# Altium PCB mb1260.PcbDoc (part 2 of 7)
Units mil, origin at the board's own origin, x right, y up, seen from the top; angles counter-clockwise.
Board outline 3189.01 x 3818.89 mil, 6 copper layers (TOP, L2_GND, L3_VCC, L4_SIG, L5_GND, BOTTOM), stack 62.2 mil thick; 308 components, 287 nets, 1220 pads, 851 vias.
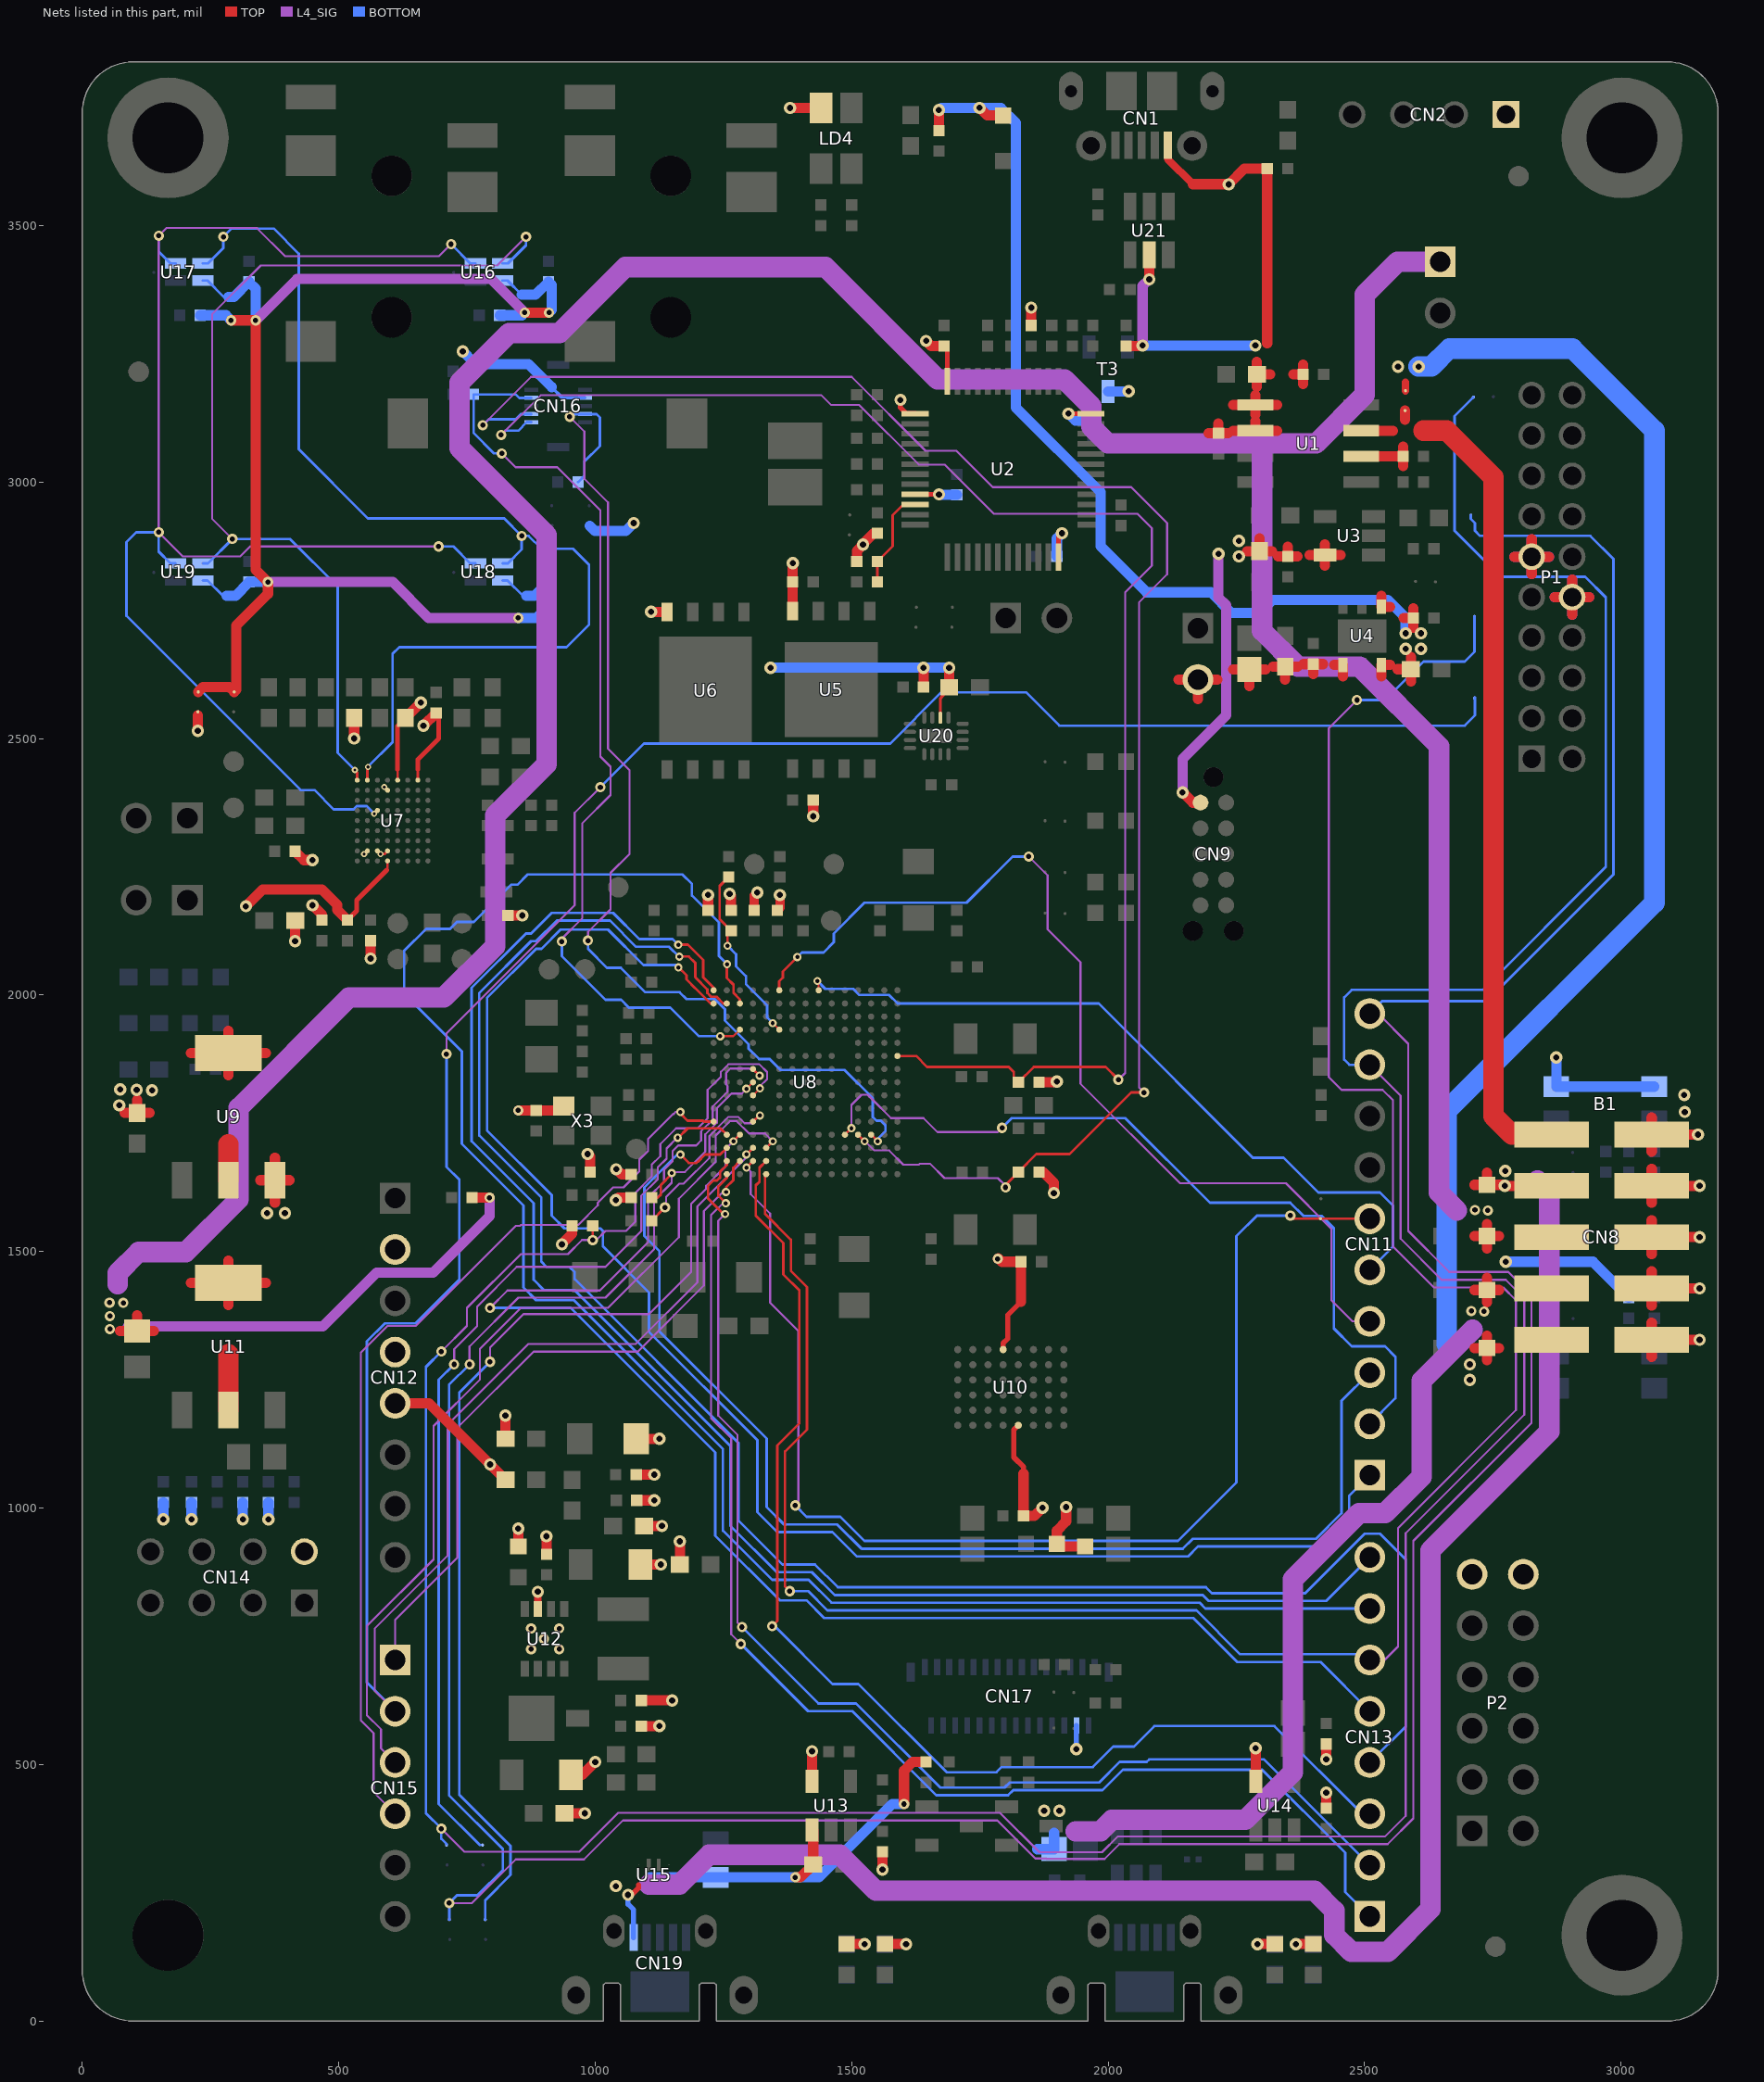
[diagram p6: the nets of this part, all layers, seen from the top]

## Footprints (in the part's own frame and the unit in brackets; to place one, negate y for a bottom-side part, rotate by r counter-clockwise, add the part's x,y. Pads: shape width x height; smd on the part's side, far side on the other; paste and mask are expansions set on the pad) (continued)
SQT-110-01-F-D-RA [mil] "SQT-110-01-F-D-RA"
  rect 52x52 hole 36: 1(-354.33,-39.37)
  round 52 hole 36: 2(-275.59,-39.37) 3(-196.85,-39.37) 4(-118.11,-39.37) 5(-39.37,-39.37) 6(39.37,-39.37) 7(118.11,-39.37) 8(196.85,-39.37) 9(275.59,-39.37) 10(354.33,-39.37) 11(-354.33,39.37) 12(-275.59,39.37) 13(-196.85,39.37) 14(-118.11,39.37) 15(-39.37,39.37) 16(39.37,39.37) 17(118.11,39.37) 18(196.85,39.37) 19(275.59,39.37) 20(354.33,39.37)
  silkscreen extent -400,-51 400,339, body extent -398,-69 407,341, height 150
SSW-106-02-F-D-RA [mil] "SSW-106-02-F-D-RA"
  rect 60x60 hole 40: 1(0,0)
  round 60 hole 40: 2(100,0) 3(200,0) 4(300,0) 5(400,0) 6(500,0) 7(0,100) 8(100,100) 9(200,100) 10(300,100) 11(400,100) 12(500,100)
  silkscreen extent -70,-13 560,495, body extent -60,-35 560,494, height 150
TACT_4SM_3R5X5R5 [mil] "TACT_4SM_3R5X5R5"
  rect 40x50 smd: 1(-33.46,95.47) 2(33.46,95.47) 3(-33.46,-95.47) 4(33.46,-95.47)
  silkscreen extent -69,-93 69,156, body extent -70,-125 70,125, height 150
TAN-A [mil] "TAN-A"
  rect 50x60 smd: 1(55,0) 2(-55,0)
  silkscreen extent -95,-45 110,45
TC2050-IDC-NL [mil] "TC2050-IDC-NL"
  round 31 smd paste-50: 1(-100,-25) 2(-50,-25) 3(0,-25) 4(50,-25) 5(100,-25) 6(100,25) 7(50,25) 8(0,25) 9(-50,25) 10(-100,25)
  round 39 hole 39: " "(-150,0) " "(150,-39.96) " "(150,39.96)
  TOP pour cut-out: -100,22.4 -100,-10.6 -89.5,-21.1 -15,-21.1 -6.9,-13 5.2,-13 13.3,-21.1 87.4,-21.1 100,-8.5 100,22.4 -100,22.4
  Keep-Out Layer circle w1: c-150,0 r35.43
  Keep-Out Layer circle w1: c150,39.96 r35.43
  Keep-Out Layer circle w1: c150,-39.96 r35.43
  silkscreen extent -245,-133 245,133, body extent -245,-133 245,133, height 150
TP_C40 [mil] "TP_C40"
  round 40 smd paste-50: 1(0,0)
  silkscreen extent -29,-29 29,29, body extent -31,-31 31,31, height 150
TSM-105-01-S-DV [mil] "TSM-105-01-S-DV"
  rect 50x145 smd: 1(-200,-97.44) 2(-200,97.44) 3(-100,-97.44) 4(-100,97.44) 5(0,-97.44) 6(0,97.44) 7(100,-97.44) 8(100,97.44) 9(200,-97.44) 10(200,97.44)
  silkscreen extent -250,-211 250,100, body extent -250,-175 250,175, height 150
XTAL_2SM_3R2X1R5 [mil] "XTAL_2SM_3R2X1R5"
  rect 51x63 smd: 1(-45.28,0) 2(45.28,0)
  silkscreen extent -85,-45 85,45, body extent -71,-30 72,32, height 150
XTAL_2SM_3R2X2R5_H1 [mil] "XTAL_2SM_3R2X2R5_H1"
  rect 71x106 smd: 1(-45.28,0) 2(45.28,0)
  silkscreen extent -95,-65 95,65, body extent -84,-56 84,56, height 150

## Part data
B1 B2: "EVQP2 - 4.7mm x 3.5 mm SMD Light Touch Switch"
C1 C2 C5 C7 C10 C12 C13 C14 C16 C23 C30 C32 C33 C36 C37 C38 C39 C40 C41 C42 C44 C45 C46 C47 C52 C53 C55 C56 C59 C60 C61 C62 C63 C69 C70 C71 C79 C80 C81 C82 C83 C84 C85 C86 C87 C93: library part Cap_100nF_X7R_10%_0402, "Capacitor,100nF,16V,X7R,10%,0402,YAGEO"
C3 C9 C11 C15 C17 C18 C24 C27 C35 C43 C50 C92: library part Cap_1uF_X5R_10%_0603, "Capacitor,1uF,16V,X5R,10%,0603,YAGEO"
C4 C6: library part Cap_10pF_NPO_5%_0402, "Capacitor,10pF,50V,NPO,5%,0402,YAGEO"
C8 C72 C76: library part Cap_10nF_X7R_10%_0603, "Capacitor,10nF,50V,X7R,10%,0603,YAGEO"
C19 C20 C21 C22 C29 C31 C77 C78: library part Cap_4.7uF_X5R_10%_0603, "Capacitor,4.7uF,16V, X5R,10%,0603,YAGEO"
C25 C26 C28 C54: library part Cap_2.2uF_X5R_10%_0603, "Capacitor,2.2uF,10V, X5R,10%,0603,YAGEO"
C34 C66: library part Cap_4.7uF_POL_10%_TANA, "Polarized Capacitor,4.7uF,16V,10%,typeA,AVX"
C48 C51: library part Cap_4.7pF_NPO_-+0.25pF_0402, "Capacitor, 4.7pF, 50V, NPO, -+0.25pF, 0402, YAGEO"
C49 C58: library part Cap_2.2uF_X7R_10%_1206, "Capacitor,2.2uF,16V, X7R,10%,1206,YAGEO"
C57: library part Cap_10uF_X5R_10%_0603, "Capacitor,10uF,6.3V,X5R,10%,0603,YAGEO"
C64 C65: library part Cap_1uF_POL_10%_TANA, "Polarized Capacitor,1uF,16V,10%,typeA,AVX"
C67: library part Cap_10uF_POL_10%_TANA, "Polarized Capacitor,10uF,10V,10%,typeA,VISHAY"
C68 C74: library part Cap_10uF_X5R_10%_0805, "Capacitor,10uF,25V,X5R,10%,0805,YAGEO"
C73 C75: library part Cap_4.7uF_X7R_10%_1206, "Capacitor,4.7uF,50V, X7R,10%,1206,AVX"
CN1: "USB-MICRO-B, 1050170001, SMT, MOLEX"
CN2: "Header, 4-Pin"
CN3: library part JP2_RA, "Header, 2-Pins, Single row, Right Angle, 2.54 mm pitch, DIP"
CN4: "Connector Jack Stereo 3.5mm, female SMT, Blue (Line input)"
CN5: "Connector Jack Stereo 3.5mm, female SMT, Green (Line output)"
CN8: library part "Header 5X2M TSM", "Header Male TSM, 5-Pin, Dual row, Straight, AMD"
CN9: library part Tag-10-C, "Tag_Connector Header, 10-Pin, Dual row No legs"
CN11: library part "Header 10X1_Female_THT", "Header, 10-Pin, Single row, female, THT, 2.54"
CN12 CN13: library part "Header 8X1_Female_THT", "Header, 8-Pins, Single row, female, THT, 2.54"
CN14: library part "Header 4X2F", "Header Female, 4-Pin, Dual row, Straight"
CN15: library part "Header 6X1_Female_THT", "Header, 6-Pins, Single row, female THT, 2.54"
CN16: library part "Header 5X2A", "Header, 5-Pin, Dual row", Manuf_1=Hirose
CN17: library part FH26-29S-0.3SHW, "29pins FPC connector", Manuf_1=Hirose
CN18 CN19: "USB-MICRO-AB, 47590-0001, SMT, MOLEX"
L1 L2 L3 L4 L5 L7 L8: library part BEAD_600R_350MA_0603, "Bead,600R,350mA,0603,FCM1608KF-601T03,Tai-tech"
L6: library part Ind_4.7uH_1A_30%, "FIXED IND 4.7UH 1A 180 MOHM 30% SMD"
LD1: library part LED_blue, "LED blue 0603"
LD2 LD3 LD5 LD7 LD10: library part LED_red, "LED red 0603"
LD4: "Bicolor Led"
LD6 LD8 LD9: library part LED_green, "LED green 0603"
P1: library part "Header 10X2 TH RA 2mm", "20 Position Receptacle Connector 0.079\" (2.00mm) Through Hole Right Angle"
P2: library part "Header 6X2 TH RA 2.54mm", "12 Position Receptacle Connector 0.100\" (2.54mm) Through Hole Right Angle"
R1 R2 R58 R92 R97: library part Res_1K_1%_0402, "Resistor,1K,0402,1%,YAGEO"
R3 R9 R15 R18 R21 R24 R67 R68 R69 R70 R71 R75: library part Res_100K_1%_0402, "Resistor,100K,0402,1%,YAGEO"
R4 R42 R44 R52 R56 R59 R60: library part Res_2K7_1%_0402, "Resistor,2K7,0402,1%,YAGEO"
R5 R35 R39 R49 R50 R53 R78 R101: library part Res_0_5%_0402, "Resistor,0,0402,5%,YAGEO"
R6 R25 R26: library part Res_4K7_1%_0402, "Resistor,4K7,0402,1%,YAGEO"
R7 R23 R51: library part Res_100_1%_0402, "Resistor,100,0402,1%,YAGEO"
R8: library part Res_36K_1%_0402, "Resistor,36K,0402,1%,YAGEO"
R10: library part Res_1K5_1%_0402, "Resistor,1K5,0402,1%,YAGEO"
R11 R17 R19 R20 R29 R30 R36 R37 R41 R43 R45 R46 R55 R57 R61 R76 R85 R86 R89 R90 R91 R93 R94 R95 R96 R102: library part Res_10K_1%_0402, "Resistor,10K,0402,1%,YAGEO"
R12: library part Res_680_1%_0402, "Resistor,680,0402,1%,YAGEO"
R13 R14: library part Res_330_1%_0402, "Resistor,330,0402,1%,YAGEO"
R16 R73 R74 R77 R79: library part Res_47K_1%_0402, "Resistor,47K,0402,1%,YAGEO"
R22: library part Res_2K2_1%_0402, "Resistor,2K2,0402,1%,YAGEO"
R27 R62 R64 R65 R72 R99: library part Res_0_5%_0603, "Resistor,0,0603,5%,YAGEO"
R28 R32 R38 R40: library part Res_22_1%_0603, "Resistor,22R,0603,1%,Yageo"
R31 R33: library part Res_20_1%_0402, "Resistor,20,0402,1%,YAGEO"
R47: library part Res_1K_1%_0603, "Resistor,1K,0603,1%,YAGEO"
R48: library part Res_510_1%_0603, "Resistor,510,0603,1%,YAGEO"
R54: library part Res_3K_1%_0402, "Resistor 3K 0402 1% YAGEO"
R63 R100: library part Res_10K_1%_0603, "Resistor,10K,0603,1%,YAGEO"
R66: library part Res_10_1%_0603, "Resistor,10,0603,1%,ROHM,1/4W"
R80: library part Res_3K3_1%_0402, "Resistor,3K3,0402,1%,YAGEO"
R81 R84: library part Res_620_1%_0603, "Resistor,620,0603,1%,VISHAY"
R82 R83: library part Res_330_1%_0603, "Resistor,330,0603,1%,YAGEO"
R98: library part Res_0_5%_0805, "Resistor,0,0805,5%,YAGEO"
SB1 SB4 SB7 SB8 SB9 SB10 SB11 SB12 SB13 SB14 SB15 SB25 SB27 SB28 SB29 SB33 SB34 SB35 SB37: library part SB_ON
SB2 SB3 SB5 SB6 SB16 SB36 SB38: library part SB_OFF
T1 T2 T3: "NPN Bipolar Transistor"
TP1 TP2 TP3 TP4 TP5 TP6 TP7 TP8 TP11 TP12 TP13 TP14 TP15: "Test Point"
U1: "1.2 A current limited high-side power switch with thermal shutdown"
U2: "Medium-density performance line ARM-based 32-bit MCU with 128KB Flash"
U3: "Ultra low drop-low noise BiCMOS voltage, regulators low ESR capacitors compatible"
U4: library part LD39050P, "Ultra low drop-low , 500 mA low quiescent current"
U5: library part MX25L51245G, "512Mb, 3V, Multiple I/O Serial Flash Memory, Quad/Dual"
U6: library part N25Q512A13GF840E, "512Mb, 3V, Multiple I/O Serial Flash Memory, Quad/Dual", Manuf_1=MICRON
U7: "Multi-Channel Audio Hub CODEC for Smartphones"
U8: "STM32F723IEK  (STM32F7 LittleBirdie) BGA176"
U9: "LOW DROP FIXED AND ADJUSTABLE POSITIVE VOLTAGE REGULATORS (1.8 Volts)"
U10: "IC SRAM 8MBIT 55NS 48MINIBGA 6mm x 8mm"
U11: "IC REG LDO 5V 0.8A SOT223"
U12: library part STLD40DPMR, "White LED power supply for large display backlight"
U13 U14: "Enhanced single channel power switches"
U15: "Common mode filter with ESD protection for USB 2.0 interface"
U16 U17 U18 U19: library part MP34DT01, "MEMS audio sensor, omnidirectional digital microphone", Manuf_1=STM
U20: "Low voltage high bandwidth quad SPDT switch"
U21 U22: "Very low capacitance ESD protection"
U23: "Dual Transil array for ESD protection"
U24: library part MCD-00251, "High power transient voltage suppressor, 7V breakdown"
X1: library part XTAL_8M_NX3225GD, "Crystal 8Mhz, 8pF, -+50PPM, SMD"
X2: library part XTAL_32K_NX3215SA, "Crystal 32.768kHz, 6pF, -+20PPM, R=50K, SMD"
X3: library part OSC_25M_NZ2520SB, "Oscillator 25.00Mhz, -+50PPM, 3.3V, Temp -55 to +125°C", Manuf_1=NDK, Manuf_Part_1=NZ2520SH-25MHZ-END4869C
Z1: library part "D Schottky", "Schottky Diode"

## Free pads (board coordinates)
  round 40 smd far side mask+40: 1(110,3215) 1(2755,145) 1(2800,3596)
  round 40 smd mask+40: ""(110,3215) ""(2755,145) ""(2800,3596)
  round 138 hole 138 unplated: ""(167.34,167.33)

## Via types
v1: diameter 24, hole 12, TOP to BOTTOM, tented both sides, 389 vias
v2: diameter 20, hole 10, TOP to BOTTOM, tented both sides, 231 vias
v3: diameter 16, hole 8, TOP to BOTTOM, tented both sides, 196 vias
v4: diameter 12, hole 6, TOP to BOTTOM, tented both sides, 35 vias

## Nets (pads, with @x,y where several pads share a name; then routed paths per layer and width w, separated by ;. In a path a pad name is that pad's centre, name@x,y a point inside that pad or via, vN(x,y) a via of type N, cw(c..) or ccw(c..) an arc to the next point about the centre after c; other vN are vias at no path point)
1V8: C20.1 C23.1 C42.1 C57.2 U7.D1 U7.D8 U7.G9 U9.2 U9.4 | length 1001.1
  TOP w5: v4(588.86,2405.36) U7.D8@595.16,2399.06 ; 593.66,2243.59 595.16,2245.09 U7.D1@595.16,2261.26 ; U7.G9@654.21,2418.74 654.21,2439.71
  TOP w9: C42.1@517,2146 535,2164 535,2184.93 593.66,2243.59 ; 654.21,2439.71 654.21,2459.21 695,2500 695,2545 C23.1@690,2550
  TOP w20: 82.78,1770 C57.2@106.8,1770 ; 106.8,1795.52 C57.2@106.8,1770 ; 130.82,1770 C57.2@106.8,1770 ; 211.98,1887.02 U9.4@285,1887.02 ; 285,1843.5 U9.4@285,1887.02 ; 285,1930.54 U9.4@285,1887.02 ; v1(319,2173) 352,2206 467,2206 497,2176 497,2165.99 C42.1@517,2146 ; 358.02,1887.02 U9.4@285,1887.02 ; v1(530,2500) C20.1@530,2540 ; v1(665,2525) C23.1@690,2550
  TOP w40: U9.2@285,1638.98 285,1708.98
  other v1: 72,1785 136,1814 106,1815 74,1816
3V3: B1.1 B1.3 C2.1 C13.2 C15.2 C16.2 C22.1 C33.1 C35.2 C41.1 C55.2 C63.2 C71.2 C92.1 CN12.2 CN12.4 CN14.2 CN16.9 CN17.26 JP1.2 L2.1 P2.6 P2.12 R27.2 R30.2 R41.1 R42.1 R43.1 R44.1 R45.1 R46.2 R52.1 R55.1 R56.2 R57.2 R59.2 R60.2 R63.2 R71.1 R73.2 R79.2 R80.1 R81.1 R82.2 R83.2 R84.2 R91.2 R93.1 R94.1 R95.1 R96.1 R100.2 R102.2 SB1.1 SB4.2 U4.4 U5.8 U6.8 U7.B2 U7.C2 U7.D2 U7.E9 U9.3 U10.D6 U10.E1 U20.2 X3.4 | length 4058
  TOP w5: v4(549.49,2274.64) U7.B2@555.79,2280.94 ; U7.C2@575.47,2280.94 v4(581.77,2274.64) 588.86,2274.64 U7.D2@595.16,2280.94 ; U7.E9@614.84,2418.74 614.84,2439.71
  TOP w6: U20.2@1672.87,2540.62 1672.87,2577.87 C92.1@1690,2600
  TOP w9: 614.84,2439.71 614.84,2524.84 C22.1@630,2540
  TOP w10: U10.E1@1795.24,1308.82 1795.24,1321.24 1804,1330 1804,1376 1830,1402 ; U10.D6@1824.76,1161.18 1816,1152.42 1816,1099 1835,1080 1835,1067
  TOP w18: R44.1@1310,2165 1310,2194 v1(1316,2200) ; R45.1@1355,2165 1360,2170 v1(1360,2195)
  TOP w20: 225,2545 225.33,2544.67 v1(225.33,2515) ; 347.53,1638.98 U9.3@375.55,1638.98 ; 375.55,1595.46 U9.3@375.55,1638.98 ; 375.55,1682.5 U9.3@375.55,1638.98 ; 403.57,1638.98 U9.3@375.55,1638.98 ; v1(415,2105) C35.2@415,2145 ; C33.1@415,2280 432,2263 v1(449,2263) ; v1(449,2175) 467,2157 C41.1@467,2146 ; v1(562,2071) R46.2@562,2106 ; C22.1@630,2540 v1(660,2570) ; L2.1@825,1135 v1(825,1180) ; R41.1@830,2155 v1(858,2155) ; v2(850,1775) C55.2@885,1775 930.04,1775 X3.4@938.58,1783.54 ; v1(935,1514) 935,1515 955,1535 R59.2@955,1550 ; v1(985,1690) 990,1685 R55.1@990,1655 ; v1(1040,1600) 1045,1605 R60.2@1070,1605 ; v1(1040.88,1660.37) 1051.25,1650 R57.2@1070,1650 ; R71.1@1090,575 v1(1125,575) ; v1(1108.84,2746.84) U6.8@1140,2746.84 ; R42.1@1220,2165 v1(1220,2195) ; v1(1262,2197) 1265,2194 R43.1@1265,2165 ; U5.8@1385,2748.54 C13.2@1385,2805 v1(1385,2842) ; v1(1425,2348.46) R30.2@1425,2380 ; R81.1@1490,150 v1(1525,150) ; v1(1560,295) R80.1@1560,330 ; R82.2@1565,150 v1(1606,150) ; R102.2@1640,2600 v1(1640,2638) ; C92.1@1690,2600 v1(1690,2638) ; v2(1784.68,1485.68) 1786,1485.68 1786,1487 1793,1480 C63.2@1830,1480 1830,1402 ; 1835,1067 C71.2@1835,985 1856.5,985 v1(1872,1000.5) ; R56.2@1865,1655 1873,1655 1894,1634 v1(1894,1614) ; R52.1@1865,1830 1898.52,1830 v1(1900,1831.48) ; v1(1918,1002) 1918,974 1900,956 R100.2@1900,930 1905,925 R63.2@1955,925 ; 2136.98,2615 JP1.2@2175,2615 ; 2175,2576.98 JP1.2@2175,2615 ; 2213.02,2615 JP1.2@2175,2615 ; 2243.48,2634.49 R27.2@2275,2634.49 ; 2275,2601.97 R27.2@2275,2634.49 ; v1(2291,150) R83.2@2325,150 ; 2306.52,2634.49 R27.2@2275,2634.49 ; 2320.98,2640 C15.2@2345,2640 ; 2345,2614.48 C15.2@2345,2640 ; v1(2366,150) R84.2@2400,150 ; 2369.02,2640 C15.2@2345,2640 ; 2380.98,2645 C16.2@2400,2645 ; 2400,2625.98 C16.2@2400,2645 ; 2419.02,2645 C16.2@2400,2645 ; R79.2@2425,415 v1(2425,445) ; v1(2425,510) R73.2@2425,540 ; 2440.58,2643.48 U4.4@2457.6,2643.48 2457.6,2621.46
  BOTTOM w6.5: 915,3185 936.09,3163.91 CN16.9@979.91,3163.91
  BOTTOM w10: v1(1938.07,530) CN17.26@1938.07,575.91
  BOTTOM w20: v1(158,978) R96.1@158,1011 ; v1(213,978) R93.1@213,1011 ; v1(313,978) R95.1@313,1011 ; v1(363,978) R94.1@363,1011 ; v1(741.84,3254.76) 762.84,3233.76 C2.1@762.84,3215.76 767.84,3215.76 781.84,3229.76 870.24,3229.76 915,3185 ; SB4.2@989.03,2914.93 991.86,2912.1 998.96,2905 1060,2905 v1(1075,2920) ; v1(1342,2638) v1(1640,2638) v1(1690,2638) ; v1(2775,1480) 2945,1480 R91.2@3015,1410 ; v1(2873.53,1878.53) B1.1@2873.53,1821.46 B1.3@3064.47,1821.46
  other v1: 360,1575 395,1575
3V3_ST_LINK: C1.1 C11.2 C12.2 C81.2 C82.2 C83.2 CN2.1 CN9.1 LD4.4 R5.2 R24.2 R25.1 T3.3 U2.1 U2.9 U2.24 U2.36 U2.48 U3.5 | length 1428.8
  TOP w9: U2.9@1623.74,2975.79 v1(1670.21,2975.79) ; C1.1@1680,3265 1686.73,3258.27 U2.48@1686.73,3196.26 ; U2.24@1903.27,2853.74 1903.27,2893.27 v1(1910,2900) ; v1(1922.76,3133.27) U2.36@1966.26,3133.27
  TOP w10: v1(1595,3160) 1595,3145 1606.73,3133.27 U2.1@1623.74,3133.27
  TOP w20: v1(1380,3729.06) LD4.4@1440.47,3729.06 ; R25.1@1510,2845 1510,2866 v1(1522,2878) 1522,2879 1543,2900 R24.2@1550,2900 ; v1(1645,3275) 1655,3265 C1.1@1680,3265 ; R5.2@1850,3305 v1(1850,3340) ; v1(2145,2395) 2165,2375 CN9.1@2180,2375 ; 2270.98,2865 C11.2@2295,2865 ; 2295,2890.52 C11.2@2295,2865 ; 2319.02,2865 C11.2@2295,2865 ; 2330.98,2855 C12.2@2350,2855 ; 2350,2874.02 C12.2@2350,2855 ; 2369.02,2855 C12.2@2350,2855 ; 2392.24,2857.6 U3.5@2422.76,2857.6 ; 2422.76,2837.08 U3.5@2422.76,2857.6 ; 2422.76,2878.12 U3.5@2422.76,2857.6 ; 2453.28,2857.6 U3.5@2422.76,2857.6
  L4_SIG w20: v1(2145,2395) 2145,2460 2230,2545 2230,2760 2215,2775 v1(2215,2860)
  BOTTOM w20: v1(1670.21,2975.79) 1671,2975 C82.2@1705,2975 ; C83.2@1900,2855 1900,2890 v1(1910,2900) ; v1(1922.76,3133.27) 1936.03,3120 C81.2@1970,3120 ; T3.3@2000,3176.69 v1(2040,3176.69)
  other v1: 2255,2855 2255,2885
5V: C14.2 C17.2 CN8.2 CN8.4 CN8.6 CN8.8 CN8.10 CN12.5 D1.1 L3.1 P1.6 P1.15 R1.1 U4.1 U4.6 U13.5 U14.5 | length 3801.3
  TOP w20: CN12.5@609.84,1203.94 676.06,1203.94 v1(795,1085) L3.1@825,1055 ; U13.5@1422.6,467.24 v1(1422.6,526) ; R1.1@1670,3685 v1(1670,3725) ; v1(1749.29,3729.29) 1764.29,3714.29 D1.1@1795,3714.29 ; U14.5@2287.6,467.24 v1(2287.6,532) ; 2532.4,2621.46 U4.6@2532.4,2643.48 2549.42,2643.48 ; 2532.4,2778.54 U4.1@2532.4,2756.52 2549.42,2756.52 ; 2564.48,2635 C17.2@2590,2635 ; 2575.98,2735 C14.2@2595,2735 ; 2590,2610.98 C17.2@2590,2635 ; 2590,2659.02 C17.2@2590,2635 ; 2595,2715.98 C14.2@2595,2735 ; 2595,2754.02 C14.2@2595,2735 ; 2791.61,2854.33 P1.6@2825.63,2854.33 ; 2825.63,2820.31 P1.6@2825.63,2854.33 ; 2825.63,2888.35 P1.6@2825.63,2854.33 ; 2859.65,2854.33 P1.6@2825.63,2854.33 ; 2870.35,2775.59 P1.15@2904.37,2775.59 ; 2904.37,2741.57 P1.15@2904.37,2775.59 ; 2904.37,2809.61 P1.15@2904.37,2775.59 ; 2938.39,2775.59 P1.15@2904.37,2775.59 ; 3059.44,1294.98 CN8.10@3059.44,1328 ; 3059.44,1361.02 CN8.10@3059.44,1328 ; 3059.44,1394.98 CN8.8@3059.44,1428 ; 3059.44,1461.02 CN8.8@3059.44,1428 ; 3059.44,1494.98 CN8.6@3059.44,1528 ; 3059.44,1561.02 CN8.6@3059.44,1528 ; 3059.44,1594.98 CN8.4@3059.44,1628 ; 3059.44,1661.02 CN8.4@3059.44,1628 ; 3059.44,1694.98 CN8.2@3059.44,1728 ; 3059.44,1761.02 CN8.2@3059.44,1728 ; v1(3150,1728) CN8.2@3059.44,1728 ; v1(3153,1328) CN8.10@3059.44,1328 ; v1(3153,1428) CN8.8@3059.44,1428 ; v1(3153,1528) CN8.6@3059.44,1528 ; v1(3153,1628) CN8.4@3059.44,1628
  L4_SIG w20: 2791.61,2854.33 P1.6@2825.63,2854.33 ; 2825.63,2820.31 P1.6@2825.63,2854.33 ; 2825.63,2888.35 P1.6@2825.63,2854.33 ; 2859.65,2854.33 P1.6@2825.63,2854.33 ; 2870.35,2775.59 P1.15@2904.37,2775.59 ; 2904.37,2741.57 P1.15@2904.37,2775.59 ; 2904.37,2809.61 P1.15@2904.37,2775.59 ; 2938.39,2775.59 P1.15@2904.37,2775.59
  BOTTOM w20: v1(1670,3725) 1674.29,3729.29 v1(1749.29,3729.29) 1790.71,3729.29 1820,3700 1820,3145 1985,2980 1985,2875 2075,2785 2200,2785 2240,2745 2295,2745 2320,2770 2545,2770 2580,2735 v1(2580,2705)
  other v1: 3124,1772 3123,1805 2580,2675 2610,2675 2610,2705
5V_ST_LINK: C5.2 CN8.1 SB3.2 U1.6 U1.7 | length 1746.6
  TOP w20: U1.6@2493.3,3050 C5.2@2575,3050 ; U1.7@2493.3,3100 2555,3100 ; 2575,3030.98 C5.2@2575,3050 ; 2575,3069.02 C5.2@2575,3050 ; 2578.81,3121.19 SB3.2@2578.81,3139.17
  TOP w40: 2615,3100 2660,3100 2751,3009 2751,1764 2787,1728 CN8.1@2864.56,1728
5V_USB_FS: CN8.7 D3.1 R99.2 | length 1668.1
  TOP w20: 2714.27,1425 D3.1@2738.29,1425 ; 2738.29,1400.98 D3.1@2738.29,1425 ; 2738.29,1449.02 D3.1@2738.29,1425 ; 2762.31,1425 D3.1@2738.29,1425
  L4_SIG w40: 1937,370 1985,370 2007,392 2267,392 2360,485 2360,861 2489,990 2540,990 2611,1061 2611,1248.06 2710.28,1347.34
  BOTTOM w20: 1861.97,335 R99.2@1894.49,335 1894.49,366.52
  other v1: 1875,410 1905,410
  other v2: 2733,1383 2708,1384
5V_USB_HS: C78.1 CN8.3 CN19.1 D5.1 R74.2 R98.2 U13.1 U15.1 | length 4292.9
  TOP w10: v1(1064,246) 1071,246 1084.47,259.47 U15.1@1084.47,265.31
  TOP w20: v2(1390,280) 1400,280 C78.1@1425,305 1425,370.36 U13.1@1422.6,372.76 ; v2(1602,423) 1602,488 1619,505 R74.2@1645,505 ; 2714.27,1630 D5.1@2738.29,1630 ; 2738.29,1654.02 D5.1@2738.29,1630 ; CN8.3@2864.56,1628 v1(2773,1628) 2771,1630 D5.1@2738.29,1630
  L4_SIG w40: 1105,266 1164,266 1222,324 1477,324 1547,254 1823.67,254 ; 1823.69,253.98 1896.31,253.98 ; 1896.33,254 2402,254 2441,215 2441,168 2474,135 2545,135 2628,218 2628,917 2860,1149 2860,1615 2837,1638
  BOTTOM w10: v1(1064,246) 1064,227.8 1074.8,217 CN19.1@1074.8,162.8
  BOTTOM w20: 1105,280 R98.2@1235,280 v2(1390,280) 1436,280 1579,423 v2(1602,423)
  other v1: 1040,263 2774,1657
5V_USB_ST_LINK: C3.2 CN1.1 CN8.9 D2.1 R2.2 R11.1 R15.2 R20.2 SB3.1 U1.1 U1.2 U21.5 | length 4054.2
  TOP w15: CN1.1@2116.53,3656.49 2116.53,3629.06 2165,3580.59 ; SB3.1@2579.67,3178.01 2579.67,3194.67
  TOP w20: R11.1@2035,3265 2066,3265 v1(2067,3266) ; v1(2080,3395) U21.5@2080,3442.76 ; 2165,3580.59 2234.41,3580.59 v1(2235,3580) 2265.59,3610.59 R2.2@2310,3610.59 2310,3270 ; 2195.98,3095 R20.2@2215,3095 ; 2215,3114.02 R20.2@2215,3095 ; 2234.02,3095 R20.2@2215,3095 ; 2243.68,3100 U1.2@2286.7,3100 ; 2243.68,3150 U1.1@2286.7,3150 ; 2286.7,3119.02 U1.2@2286.7,3100 ; 2286.7,3130.98 U1.1@2286.7,3150 ; 2286.7,3169.02 U1.1@2286.7,3150 ; 2290,3185.98 C3.2@2290,3210 ; 2290,3234.02 C3.2@2290,3210 ; 2315.52,3210 C3.2@2290,3210 ; 2329.72,3100 U1.2@2286.7,3100 ; 2329.72,3150 U1.1@2286.7,3150 ; 2360.98,3210 R15.2@2380,3210 ; 2380,3190.98 R15.2@2380,3210 ; 2380,3229.02 R15.2@2380,3210 ; 2714.27,1312 D2.1@2738.29,1312 ; 2738.29,1287.98 D2.1@2738.29,1312 ; 2738.29,1336.02 D2.1@2738.29,1312 ; 2762.31,1312 D2.1@2738.29,1312
  L4_SIG w20: v1(2067,3266) 2067,3382 v1(2080,3395)
  BOTTOM w20: v1(2067,3266) v1(2287,3266)
  BOTTOM w40: v1(2605,3225) 2630,3225 2665,3260 2905,3260 3065,3100 3065,2180 2660,1775 2660,1320 2665,1315
  other v1: 2705,1250 2705,1280 2565,3225
AIN_1: R25.2 R26.2 U2.10 | length 195.1
  TOP w5: R26.2@1550,2805 R25.2@1550,2845 1580,2875 1580,2935.29 1600.81,2956.1 U2.10@1623.74,2956.1
ARD_A0: CN15.1 U8.P3 | length 1373.5
  TOP w5: v3(1255,1616) 1255,1625 1268.96,1638.96 1268.96,1663.24 1282.05,1676.33 U8.P3@1282.05,1676.46
  L4_SIG w4: CN15.1@609.84,703.94 609.84,781.84 731.5,903.5 731.5,1156.5 880,1305 1083.23,1305 1212,1433.77 1212,1579 1249,1616 v3(1255,1616)
ARD_A1: CN15.2 SB28.2 U8.N4 | length 5462.6
  TOP w5: v3(1294.78,1689.32) 1294.91,1689.32 U8.N4@1307.64,1702.05
  L4_SIG w4: CN15.2@609.84,603.94 570,643.78 570,765 712.5,907.5 712.5,1162.5 870,1320 1079,1320 1199,1440 1199,1588 1294.78,1683.78 v3(1294.78,1689.32) ; v2(710,1885) 710,1925 960,2175 960,2355 v2(1010,2405)
  BOTTOM w5: CN15.2@609.84,603.94 609.84,605.16 555,660 555,1325 590,1360 650,1360 735,1445 735,1640 710,1665 v2(710,1885) ; v2(1010,2405) 1095,2490 1575,2490 1675,2590 1840,2590 1905,2525 2695,2525 2715,2545 SB28.2@2715,2580
ARD_A2: CN15.3 U8.N5 | length 1783.5
  TOP w5: U8.N5@1333.23,1702.05 1345.96,1714.78 v3(1346.09,1714.78)
  L4_SIG w4: CN15.3@609.84,503.94 582.39,531.39 582.39,568.61 555,596 555,770 685,900 685,1160 775,1250 775,1310 855,1390 1025,1390 1163,1528 1163,1602.94 1235,1674.94 1235,1725.98 1263.47,1754.45 1275.3,1754.45 1299.75,1730 1330.87,1730 v3(1346.09,1714.78)
ARD_A3: CN15.4 U8.L1 | length 1848.5
  TOP w5: v3(1166,1772) 1166,1769.01 1179.87,1755.14 1210.09,1755.14 1212,1753.23 U8.L1@1230.87,1753.23
  L4_SIG w4: CN15.4@609.84,403.94 568,445.78 568,561 543,586 543,1303 595,1355 650,1355 845,1550 853.02,1550 855.02,1552 967,1552 1005,1590 1005,1595 1035,1625 1055.08,1625 1086.03,1655.95 1086.03,1679.11 1103,1696.08 1103,1719.25 1151.75,1768 1153,1768 1157,1772 v3(1166,1772)
ARD_A4: SB35.1 U8.M2 | length 1815.4
  TOP w5: v3(1160.8,1721.87) 1161.87,1721.87 1180.14,1740.14 1243.96,1740.14 U8.M2@1256.46,1727.64
  L4_SIG w4: v2(725,1280) 725,1310 770,1355 770,1393.02 846.98,1470 1020,1470 1090,1540 1090,1608.98 1122.03,1641.01 1122.03,1664.17 1139,1681.14 1139,1700.98 1159.89,1721.87 v3(1160.8,1721.87)
  BOTTOM w5: v2(725,1280) 695,1250 695,423.34 775.33,343.01
ARD_A5: SB37.1 U8.M3 | length 1961.8
  TOP w5: v3(1269.27,1714.86) U8.M3@1282.05,1727.64
  L4_SIG w4: v2(795,1285) 795,1313.02 859.98,1378 1105,1378 1187,1460 1187,1592.98 1216.44,1622.42 1216.44,1628.08 1254,1665.64 1254,1699.59 v3(1269.27,1714.86)
  BOTTOM w5: SB37.1@785.53,197.87 785.53,235.53 835,285 835,341.22 735,441.22 735,1225 v2(795,1285)
ARD_D0: CN13.1 U8.R2 | length 2499.6
  TOP w5: v3(1254.45,1594) 1240,1608.45 1240,1627.04 1256.46,1643.5 U8.R2@1256.46,1650.87
  L4_SIG w4: v3(1254.45,1594) 1249,1594 1226,1571 1226,1175 1265.1,1135.9 1265.1,753.9 v2(1284,735)
  BOTTOM w5: v2(1284,735) 1415,604 1501,604 1665,440 1805,440 1815,450 1988.66,450 2028.66,490 2300,490 2462,328 2462,251.78 CN13.1@2509.84,203.94
ARD_D1: CN13.2 U8.P2 | length 2429.2
  TOP w5: v3(1253,1573) 1250,1573 1220.07,1602.93 1220.07,1628.24 1230.2,1638.37 1237.34,1638.37 1243.37,1644.4 1243.37,1655.46 1256.46,1668.55 U8.P2@1256.46,1676.46
  L4_SIG w4: v3(1253,1573) 1240,1560 1240,1180 1277.5,1142.5 1277.5,776.5 v2(1286,768)
  BOTTOM w5: v2(1286,768) 1435,619 1508.56,619 1672.56,455 1798,455 1808,465 1982.44,465 2022.44,505 2075,505 2080,510 2303.78,510 CN13.2@2509.84,303.94
ARD_D2: CN13.3 U8.P5 | length 2363.2
  TOP w5: U8.P5@1333.23,1676.46 1320.14,1663.37 1320.14,1636.13 1313,1628.99 1313,1570.22 1366.5,1516.72 1366.5,1455.5 1398,1424 1398,1165 1355,1122 1355,780 1345,770 v2(1345,769.75)
  BOTTOM w5: v2(1345,769.75) 1350,769.75 1462.75,657 1513,657 1685,485 1782,485 1792,495 1970,495 2010,535 2050,535 2090,575 2324,575 2495.06,403.94 CN13.3@2509.84,403.94
ARD_D3: CN13.4 U8.B2 | length 3746
  TOP w5: v3(1163.97,2074.74) 1165,2074.74 1165,2075 1182.56,2075 1195,2062.56 1195,2035 1195.5,2034.5 1195.5,2033.78 1218.37,2010.91 1218.37,2003.95 1225.69,1996.63 1236.37,1996.63 1249.46,1983.54 U8.B2@1256.46,1983.54
  BOTTOM w5: v3(1163.97,2074.74) 1163.33,2074.74 1144.07,2094 1079.62,2094 1028.62,2145 925,2145 885,2105 875,2105 774,2004 774,1726 895,1605 895,1480 905,1470 950,1470 960,1460 960,1445.88 1279,1126.88 1279,976 1365,890 1428.44,890 1472.94,845.5 2190.6,845.5 2202.16,833.94 2383.94,833.94 2500,950 2530,950 2580,900 2580,574.1 CN13.4@2509.84,503.94
ARD_D4: CN13.5 U8.G4 | length 3005.1
  TOP w5: U8.G4@1307.64,1855.59 v3(1320.37,1842.86)
  L4_SIG w4: v2(795,1390) 829,1424 1009,1424 1103,1518 1103,1604.98 1105,1606.98 1134.03,1636.03 1134.03,1659.19 1151,1676.16 1151,1696 1161.87,1706.87 1196.87,1706.87 1206.5,1716.5 1206.5,1734.5 1229,1757 1229,1782.61 1257.79,1811.4 1257.79,1823 1255,1825.79 1255,1848.21 1263.52,1856.73 1306.5,1856.73 v3(1320.37,1842.86)
  BOTTOM w5: v2(795,1390) 952.22,1390 1234,1108.22 1234,946 1360,820 1412,820 1446.5,785.5 2165.72,785.5 2251.22,700 2413.78,700 CN13.5@2509.84,603.94
ARD_D5: CN13.6 SB29.2 U8.R5 | length 4698.6
  TOP w5: U8.R5@1333.23,1650.87 1331,1648.64 1331,1573.44 1381.5,1522.94 1381.5,1462.28 1413,1430.78 1413,1153 1370,1110 1370,847 v2(1379,838)
  L4_SIG w4: v2(2485,2575) 2430,2520 2430,1840 2455,1815 2535,1815 2555,1795 2555,1510 2635,1430 2770,1430 2795,1405 2795,1191 2565,961 2565,730 2538.94,703.94 CN13.6@2509.84,703.94
  BOTTOM w5: v2(1379,838) 1415.22,838 1452.72,800.5 2171.94,800.5 2257.44,715 2498.78,715 CN13.6@2509.84,703.94 ; v2(2485,2575) 2540,2575 2615,2650 2695,2650 2714.17,2669.17 SB29.2@2714.17,2737.81
ARD_D6: CN13.7 U8.B3 | length 3656.8
  TOP w5: v3(1257,2060) 1256.5,2059.5 1256.5,2033.04 1269.55,2020 1269.55,2003.94 1282.05,1991.44 U8.B3@1282.05,1983.54
  BOTTOM w5: v3(1257,2060) 1241,2076 1241,2141.24 1188.5,2193.74 1188.5,2216.3 1169.8,2235 868,2235 848,2215 835.97,2215 763.47,2142.5 730.5,2142.5 717,2129 670.22,2129 627.5,2086.28 627.5,2002.5 740,1890 740,1710 860,1590 860,1430 885,1405 958.44,1405 1249,1114.44 1249,956 1345,860 1416,860 1460.5,815.5 2178.16,815.5 2189.72,803.94 CN13.7@2509.84,803.94
ARD_D7: CN13.8 U8.A1 | length 3252.4
  TOP w5: v3(1162,2098) 1180.78,2098 1210.5,2068.28 1210.5,2034.5 1230.87,2014.13 U8.A1@1230.87,2009.13
  BOTTOM w5: v3(1162,2098) 1151,2109 1085.84,2109 1034.84,2160 915,2160 875,2120 865,2120 759,2014 759,1715 880,1594 880,1445 900,1425 959.66,1425 1264,1120.66 1264,964.78 1353.78,875 1422.22,875 1466.72,830.5 2184.38,830.5 2195.94,818.94 2424.84,818.94 CN13.8@2509.84,903.94
ARD_D8: CN11.1 U8.B1 | length 3142.4
  TOP w5: v3(1162.06,2053.82) 1162.08,2054.14 1177.78,2038.44 1177.78,2030.49 1180.5,2027.77 1180.5,2027.56 1193.79,2014.27 1194,2014.27 1224.73,1983.54 U8.B1@1230.87,1983.54
  BOTTOM w5: v3(1162.06,2053.82) 1162.08,2053.97 1157.43,2058.62 1093.78,2058.62 1024.9,2127.5 932.5,2127.5 895,2090 885,2090 789,1994 789,1736 915,1610 915,1570 940,1545 1010,1545 1015,1540 1015,1510 1105,1420 1105,1343.32 1316,1132.32 1316,992 1355,953 1462.5,953 1510,905.5 2155.5,905.5 2175,925 2411.34,925 2470,983.66 2470,1024.1 CN11.1@2509.84,1063.94
ARD_D9: CN11.2 U8.M11 | length 1632.1
  TOP w5: U8.M11@1486.77,1727.64 v3(1499.5,1740.37)
  L4_SIG w4: v3(1499.5,1740.37) 1499.5,1785.63 1519.42,1805.55 1531.02,1805.55 1539.22,1797.35 1539.33,1797.35 1576.68,1760 1640,1760 1667.18,1732.82 1784.85,1732.82 v2(1792.99,1740.96)
  BOTTOM w5: v2(1792.99,1740.96) 1812.03,1760 2033.22,1760 2198.22,1595 2355,1595 2380.61,1569.39 2415.61,1569.39 2440,1545 2440,1350 2475,1315 2540,1315 2560,1295 2560,1214.1 CN11.2@2509.84,1163.94
ARD_D10: CN11.3 U8.N2 | length 2407.9
  TOP w5: v3(1166,1689) 1182.49,1672.51 1197.26,1672.51 1199.75,1675 1200,1675 1213.96,1688.96 1243.37,1688.96 U8.N2@1256.46,1702.05
  BOTTOM w5: v3(1166,1689) 1160,1689 1096,1625 1096,1530 1125,1501 1125,1344.54 1334,1135.54 1334,1002 1368,968 1471.78,968 1518.78,921 1519,921 1519.5,920.5 2145.5,920.5 2165,940 2405.12,940 2455,989.88 2455,1209.1 CN11.3@2509.84,1263.94
ARD_D11: CN11.4 U8.A6 | length 1943.7
  TOP w5: U8.A6@1358.82,2009.13 1358.82,2026.87 1365.73,2033.78 1365.73,2045.73 v3(1394,2074)
  L4_SIG w4: v2(1845,2270) 1882,2233 1882,2128 1946,2064 1946,1827.02 2140.02,1633 2346.39,1633 2435,1544.39 2435,1405 2476.06,1363.94 CN11.4@2509.84,1363.94
  BOTTOM w5: v3(1394,2074) 1403,2083 1444.93,2083 1465,2103.07 1465,2120 1525,2180 1723.78,2180 1813.78,2270 v2(1845,2270)
ARD_D12: CN11.5 U8.A9 | length 1467.3
  TOP w4: v3(1433,2027.41) 1435.59,2024.82 U8.A9@1435.59,2009.13
  BOTTOM w5: v3(1433,2027.41) 1448.41,2012 1503,2012 1515,2000 1572.98,2000 1589.48,1983.5 1981.5,1983.5 2282,1683 2342,1683 2410,1615 2530,1615 2555,1590 2555,1509.1 CN11.5@2509.84,1463.94
ARD_D13: CN11.6 SB14.2 U8.P4 | length 2415.8
  TOP w5: v3(1294.9,1663.6) 1295.5,1664.2 1295.5,1664.32 U8.P4@1307.64,1676.46 ; v2(2355.13,1570) 2360.96,1564.17 SB14.2@2413.81,1564.17 2509.61,1564.17 CN11.6@2509.84,1563.94
  L4_SIG w4: v3(1294.9,1663.6) 1303,1655.5 1303,1612 1341,1574 1341,1400 1396,1345 1396,1011 v2(1390,1005)
  BOTTOM w5: v2(1390,1005) 1412,983 1478,983 1525,936 2136,936 2250,1050 2250,1530 2290,1570 v2(2355.13,1570)
ARD_D14: CN11.9 R59.1 SB27.1 SB36.1 U8.J4 | length 7754.5
  TOP w4: U8.J4@1307.64,1804.41 1320.05,1816.82 1320.05,1816.99 v3(1321.12,1818.06)
  TOP w5: R59.1@995,1550 995,1522.37 v2(995.13,1522.37)
  L4_SIG w4: v2(700,375) 745,330 969,330 1045,406 1789,406 1866,329 1988,329 2019,360 2540,360 2580,400 2580,951 2811,1182 2811,1409 2775,1445 2650,1445 2570,1525 2570,1803.78 CN11.9@2509.84,1863.94 ; v2(700,1305) 750,1355 750,1390 855,1495 946.8,1495 974.17,1522.37 v2(995.13,1522.37) 1002.37,1522.37 1020,1540 1060,1540 1078,1558 1078,1613.96 1110.03,1645.99 1110.03,1669.15 1127,1686.12 1127,1709.29 1157.71,1740 1199.59,1740 1219,1759.41 1219,1815 1245,1841 1245,1850.32 1259.68,1865 1320,1865 1335,1850 1335,1836 1321.12,1822.12 v3(1321.12,1818.06)
  BOTTOM w5: v2(700,1305) 670,1275 670,405 v2(700,375) 700,355 SB36.1@710,345 ; CN11.9@2509.84,1863.94 2470,1863.94 2460,1873.94 2460,1995 2475,2010 2730,2010 2970,2250 2970,2775 2930,2815 2765,2815 2675,2905 2675,3128.34 SB27.1@2711.99,3165.33
ARD_D15: CN11.10 R60.1 SB25.1 SB38.1 U8.H4 | length 7594.4
  TOP w4: v3(1294.78,1817.14) U8.H4@1307.64,1830
  TOP w5: R60.1@1110,1605 1122,1605 1128,1611 1128,1630 1149.03,1651.03 v3(1149.03,1652.97)
  L4_SIG w4: v2(715.53,230) 760,230 845,315 978,315 1054,391 1765.7,391 1782.28,391.01 1784,391 1858,317 1879.48,317 1880.48,316 1993,316 2022,345 2545,345 2595,395 2595,936 2825,1166 2825,1415 2780,1460 2665,1460 2585,1540 2585,1905 2526.06,1963.94 CN11.10@2509.84,1963.94 ; v2(755,1280) 755,1315 850,1410 1020,1410 1115,1505 1115,1600 1149.03,1634.03 v3(1149.03,1652.97) 1151.06,1655 1175,1655 1214.5,1694.5 1214.5,1728.5 1237,1751 1237,1779.29 1265.71,1808 1285.64,1808 v3(1294.78,1817.14)
  BOTTOM w5: SB38.1@715.53,197.87 v2(715.53,230) 730.53,245 770,245 820,295 820,335 715,440 715,1240 v2(755,1280) ; CN11.10@2509.84,1963.94 2533.9,1988 2738,1988 2985,2235 2985,2850 2940,2895 2725,2895 2715,2905 2715,2920 2706.99,2928.01 SB25.1@2706.99,2935.33
BLGND: C67.2 C69.1 C70.1 C72.1 C73.1 C75.1 C76.1 L5.2 R66.1 R67.1 R69.1 U12.3 U12.9 | length 495.1
  TOP w15: U12.3@888.2,803.07 v1(888.2,836.8)
  TOP w20: R66.1@850,925 v1(850,960) ; R67.1@905,910 v1(905,945) ; C76.1@940,405 v1(980,405) ; C75.1@953,480 975,480 v1(1000,505) ; C69.1@1080,1065 v1(1115,1065) ; C67.2@1080,1135 v1(1125,1135) ; C70.1@1081,1015 v1(1115,1015) ; C73.1@1088,890 v1(1128,890) ; R69.1@1090,625 v1(1150,625) ; C72.1@1095,965 v1(1130,965) ; L5.2@1165,890 v1(1165,935)
  other v2: 875,725 930,725 900,745 875,765 930,765
BOOT0: R36.2 R43.2 U8.D6 | length 358.9
  TOP w4: v3(1345.96,1945.22) U8.D6@1358.82,1932.36
  TOP w5: v3(1258,2096) 1258,2118 R43.2@1265,2125 1242.5,2147.5 1242.5,2212.5 R36.2@1260,2230
  BOTTOM w5: v3(1258,2096) 1274.5,2079.5 1274.5,2056.08 1293.81,2036.77 1293.81,2021.19 1335,1980 1335,1956.18 v3(1345.96,1945.22)
BYPASSREG: R61.2 U8.L4 | length 360.5
  TOP w5: R61.2@1110,1560 v2(1136,1586) ; U8.L4@1307.64,1753.23 1307.64,1753.35 1319.42,1765.13 v3(1321.16,1765.13)
  L4_SIG w4: v2(1136,1586) 1138,1588 1138,1606.02 1164.03,1632.05 1172.05,1632.05 1222.5,1682.5 1222.5,1725.18 1259.77,1762.45 1278.62,1762.45 1291.07,1750 1305,1750 1320.13,1765.13 v3(1321.16,1765.13)
CTP_INT: CN16.2 R21.2 U8.D3 | length 1834
  TOP w4: v3(1243.68,1919.68) 1269.36,1919.68 U8.D3@1282.04,1932.36
  L4_SIG w4: v2(817.84,3055.76) 844.64,3028.96 926.04,3028.96 1010,2945 1010,2465 1030,2445 1030,2390 975,2335 975,2150 935,2110 v2(935,2104.38)
  BOTTOM w5: v2(817.84,3055.76) 802.84,3055.76 762.84,3095.76 R21.2@762.84,3170.76 845,3170.76 851.85,3163.91 CN16.2@875.57,3163.91 ; v2(935,2104.38) 935,2075.78 1020.28,1990.5 1050.5,1990.5 1065.5,1975.5 1146.5,1975.5 1202.32,1919.68 v3(1243.68,1919.68)
CTP_RST: CN16.7 R18.2 U8.M13 | length 2144.3
  TOP w5: U8.M13@1537.95,1727.64 v3(1550.81,1714.78)
  L4_SIG w4: v2(950.04,3127.21) 978.84,3098.41 978.84,3006.16 1025,2960 1025,2480 1067,2438 1067,2274.98 1030,2237.98 1030,2167 986,2123 v2(986,2106)
  BOTTOM w5: v2(950.04,3127.21) 955.24,3132.41 CN16.7@979.91,3132.41 1002.59,3132.41 1008.96,3126.04 1008.96,3070.12 978.84,3040 978.84,3011.76 R18.2@966.84,2999.76 ; v2(986,2106) 986,2089.86 1022.88,2052.98 1050.02,2052.98 1097.5,2005.5 1164.28,2005.5 1177.78,1992 1233,1992 1252.73,1972.27 1252.73,1950 1299,1903.73 1299,1895.49 1319.49,1875 1340,1875 1361.05,1853.95 1486.05,1853.95 1541,1799 1541,1762 1548,1755 1556,1755 1556.13,1754.87 1556.82,1754.87 1565.31,1746.38 1565.31,1745.69 1566,1745 1566,1735 1550.81,1719.81 v3(1550.81,1714.78)
CTP_SCL: CN16.5 R52.2 U8.F15 | length 3060.2
  TOP w5: U8.F15@1589.13,1881.18 1625.77,1881.18 1646.95,1860 1806,1860 1816,1850 1816,1839 R52.2@1825,1830 1855,1860 1995,1860 v2(2020,1835)
  L4_SIG w4: v2(816.57,3091.76) 893.81,3169 1441,3169 1460,3150 1515,3150 1631,3034 1681,3034 1777,2938 2057,2938 2085,2910 2085,2837 2033,2785 2033,1848 v2(2020,1835)
  BOTTOM w5: v2(816.57,3091.76) 824.81,3100 850,3100 866.66,3116.66 CN16.5@875.57,3116.66
CTP_SDA: CN16.4 R56.1 U8.M12 | length 3415
  TOP w5: U8.M12@1512.36,1727.64 v3(1525.22,1714.78) ; v2(1800,1625) 1800,1630 R56.1@1825,1655 1860,1690 1925,1690 2045,1810 v2(2070,1810)
  L4_SIG w4: v2(780.84,3110.76) 875.08,3205 1500,3205 1644,3061 1704,3061 1775,2990 2045,2990 2115,2920 2115,2820 2060,2765 2060,1820 v2(2070,1810) ; v3(1525.22,1714.78) 1526.22,1714.78 1544,1697 1573.01,1697 1600.7,1669.3 1631.02,1669.3 1632.98,1671.26 1652.61,1671.26 1680.88,1642.99 1690.82,1642.99 ; 1690.83,1643 1785,1643 1800,1628 v2(1800,1625)
  BOTTOM w5: v2(780.84,3110.76) 792.54,3122.46 845.05,3122.46 855,3132.41 CN16.4@875.57,3132.41
DMIC_VDD: C79.1 C80.1 C84.1 C85.1 R85.2 R86.2 SB1.2 SB5.2 U16.1 U17.1 U18.1 U19.1 | length 2901.9
  TOP w20: SB1.2@226.19,2590.83 235.36,2600 287.02,2600 SB5.2@296.19,2590.83 300,2594.64 300,2720 362,2782 v2(362,2805) 338,2829 v2(338,3315) v2(290,3315) ; v2(862.61,3330.28) 862.89,3330 v2(910,3330)
  L4_SIG w20: v2(338,3315) 419,3396 796.89,3396 v2(862.61,3330.28) ; v2(362,2805) 605,2805 675,2735 v2(850,2735)
  BOTTOM w5: U19.1@235.03,2808.07 244.32,2808.07 274.39,2778 281.39,2778 ; U17.1@235.03,3392.68 244.32,3392.68 276,3361 285,3361 ; U18.1@819.64,2808.07 828.93,2808.07 859,2778 866,2778 ; U16.1@819.64,3392.68 828.93,3392.68 856.61,3365
  BOTTOM w20: R86.2@230,3325 280,3325 v2(290,3315) ; 281.39,2778 299,2778 325,2804 C85.1@325,2805 v2(362,2805) ; 285,3361 296,3361 C80.1@325,3390 338,3377 v2(338,3315) ; R85.2@813.74,3325 857.33,3325 v2(862.61,3330.28) ; v2(850,2735) 885,2735 908.74,2758.74 C84.1@908.74,2805 881.74,2778 866,2778 ; 856.61,3365 883.74,3365 C79.1@908.74,3390 915,3383.74 915,3335 v2(910,3330)
DMICCLK: U7.C6 U16.3 U17.3 U18.3 U19.3 | length 2933.4
  TOP w5: v4(569.17,2353.39) U7.C6@575.47,2359.69
  L4_SIG w4: v2(694.61,2874.39) 327.39,2874.39 308,2855 196,2855 v2(149,2902) v2(149,3480) 164,3495 340.51,3495 395.51,3440 695.39,3440 v2(719,3463.61)
  BOTTOM w5: v2(149,3480) 149,3449 171.86,3426.14 U17.3@181.89,3426.14 ; U19.3@181.89,2841.53 171.86,2841.53 149,2864.39 v2(149,2902) 105,2902 86,2883 86,2739 425.5,2399.5 452.5,2399.5 490,2362 529,2362 535,2368 554.56,2368 v4(569.17,2353.39) ; v2(694.61,2874.39) 723.61,2874.39 756.47,2841.53 U18.3@766.5,2841.53 ; v2(719,3463.61) 756.47,3426.14 U16.3@766.5,3426.14
DMICDAT1: U7.B9 U17.4 U18.4 | length 2153
  TOP w5: U7.B9@555.79,2418.74 555.79,2443.43 v4(557,2444.64)
  BOTTOM w5: U17.4@235.03,3426.14 245.14,3426.14 275,3456 v2(275,3478) 291,3494 373,3494 422,3445 422,3064 557,2929 822.61,2929 v2(856.61,2895) ; v4(557,2444.64) 605,2492.64 605,2665 618,2678 944,2678 988,2722 988,2838.25 956.25,2870 895.25,2870 870.25,2895 v2(856.61,2895) ; U18.4@819.64,2841.53 829.75,2841.53 856.61,2868.39 v2(856.61,2895)
DMICDAT2: U7.A9 U16.4 U19.4 | length 1919.7
  TOP w5: v4(531.25,2438.58) 536.1,2433.73 U7.A9@536.1,2418.74
  L4_SIG w4: v2(292.5,2888.89) 253,2928.39 253,3327 348,3422 809,3422 v2(865,3478)
  BOTTOM w5: U19.4@235.03,2841.53 245.14,2841.53 v2(292.5,2888.89) 405.11,2888.89 498,2796 498,2471.83 v4(531.25,2438.58) ; U16.4@819.64,3426.14 829.75,3426.14 865,3461.39 v2(865,3478)
E5V: C68.2 CN3.1 CN8.5 D4.1 R58.2 U11.2 U11.4 | length 7889.7
  TOP w20: 73.78,1345 C68.2@106.8,1345 ; 106.8,1375.52 C68.2@106.8,1345 ; 139.82,1345 C68.2@106.8,1345 ; 211.98,1439.02 U11.4@285,1439.02 ; 285,1395.5 U11.4@285,1439.02 ; 285,1482.54 U11.4@285,1439.02 ; 358.02,1439.02 U11.4@285,1439.02 ; R58.2@760,1605 v2(794,1605) ; 2714.27,1530 D4.1@2738.29,1530 ; 2738.29,1505.98 D4.1@2738.29,1530 ; 2738.29,1554.02 D4.1@2738.29,1530 ; 2762.31,1530 D4.1@2738.29,1530
  TOP w40: U11.2@285,1190.98 285,1300
  L4_SIG w20: 89,1354 469,1354 573.94,1458.94 683.94,1458.94 794,1569 v2(794,1605)
  L4_SIG w40: 69,1436 69,1458 110,1499 202,1499 305,1602 305,1780 520,1995 705,1995 805,2095 805,2350 905,2450 905,2896.73 735.54,3066.19 735.54,3193.49 832.05,3290 930,3290 1059,3419 1448.67,3419 1667.67,3200 1915,3200 1967.5,3147.5 1967.5,3107.5 2000,3075 2300,3075 ; CN3.1@2647.2,3429.41 2564.41,3429.41 2500,3365 2500,3170 2405,3075 2300,3075 ; 2680,1580 2645,1615 2645,2485 2490,2640 2370,2640 2300,2710 2300,3075
  other v2: 54,1349 54,1374 53.25,1400.38 80.19,1399.78 2740,1580 2715,1581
